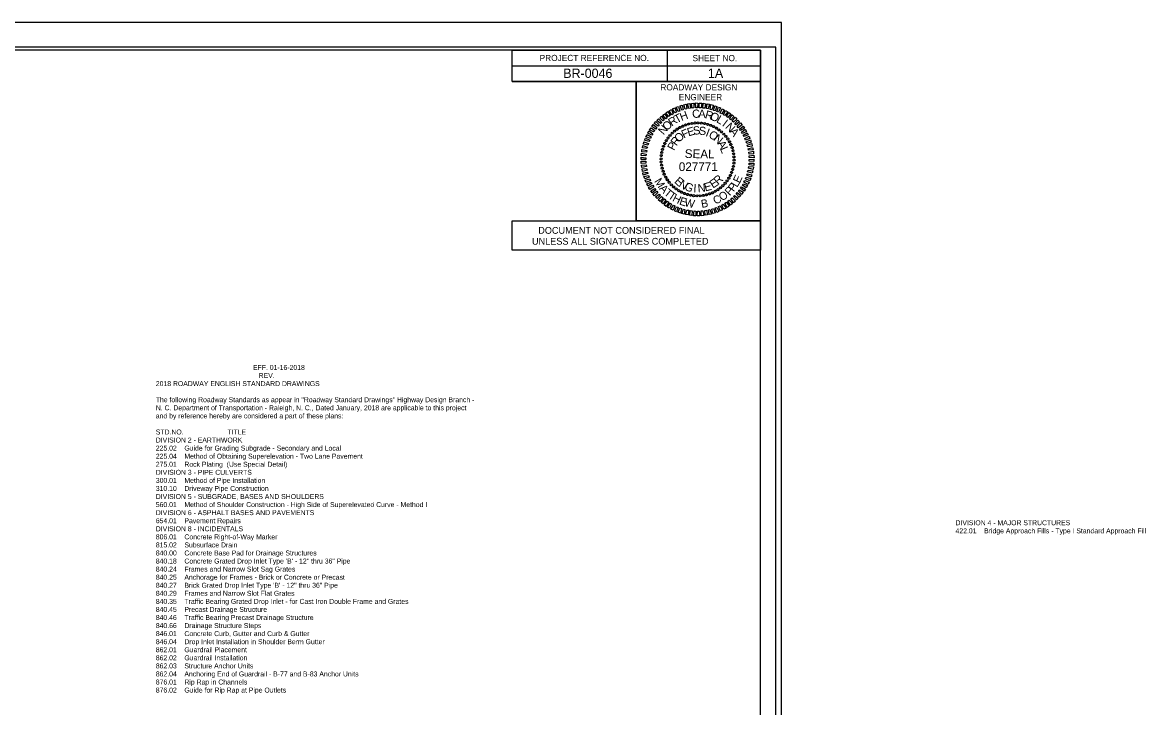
# Model space of a CAD drawing. Extents: x 1983800 to 2121016, y 627229 to 697309.
# Drawn here: x 2052408 to 2110005, y 661964 to 697309 of the extents above; entities that cross this region are included whole.
import ezdxf

# ---------------------------------------------------------------- set-up
doc = ezdxf.new("R2010")
doc.units = 0
for name, color, linetype in [('Sheet Cutting Line CELL', 7, 'Continuous'), ('Sheet Data Field CELL', 7, 'Continuous'), ('Sheet Data Text CELL', 7, 'Continuous'), ('Sheet Plan CELL', 7, 'Continuous'), ('Sheet Plot Border Inside CELL', 7, 'Continuous'), ('Sheet Plot Border Outside CELL', 7, 'Continuous'), ('Sheet Professional Seal CELL', 7, 'Continuous'), ('Sheet Sticker Exception Certification CELL', 7, 'Continuous')]:
    doc.layers.add(name, color=color, linetype=linetype)

msp = doc.modelspace()

# ---------------------------------------------------------------- linework, layer by layer
at = {"layer": 'Sheet Cutting Line CELL'}
msp.add_line((2091544, 697309), (1983800, 697309), dxfattribs=at)
at = {"layer": 'Sheet Plan CELL'}
for p, q in [((2085656, 695866), (2085656, 694266)), ((2077653, 695066), (2090456, 695066)), ((2077653, 694266), (2090456, 694266)), ((2077653, 694266), (2090456, 694266)), ((2084056, 694266), (2084056, 687069))]:
    msp.add_line(p, q, dxfattribs=at)
for points in [[(2090456, 695869), (1994456, 695869), (1994456, 628669), (2090456, 628669)], [(2077653, 695869), (2090456, 695869), (2090456, 694266), (2077653, 694266)], [(2084056, 694266), (2090456, 694266), (2090456, 687066), (2084056, 687066)]]:
    msp.add_lwpolyline(points, close=True, dxfattribs=at)
at = {"layer": 'Sheet Plot Border Inside CELL'}
msp.add_lwpolyline([(1984632, 628509), (2091256, 628509), (2091256, 696029), (1984632, 696029)], close=True, dxfattribs=at)
at = {"layer": 'Sheet Plot Border Outside CELL'}
msp.add_lwpolyline([(1983800, 627229), (2091544, 627229), (2091544, 697309), (1983800, 697309)], close=True, dxfattribs=at)
at = {"layer": 'Sheet Professional Seal CELL'}
for p, q in [((2086162, 691799), (2086162, 691799)), ((2086305, 691885), (2086305, 691885)), ((2086451, 691960), (2086451, 691960)), ((2086601, 692020), (2086601, 692020)), ((2086758, 692065), (2086758, 692065)), ((2086923, 692095), (2086923, 692095)), ((2087085, 692118), (2087085, 692118)), ((2087250, 692121), (2087250, 692121)), ((2087415, 692110), (2087415, 692110)), ((2087576, 692084), (2087576, 692084)), ((2087733, 692050), (2087733, 692050)), ((2087891, 691998), (2087891, 691998)), ((2088041, 691930), (2088041, 691930)), ((2088187, 691855), (2088187, 691855)), ((2088322, 691761), (2088322, 691761)), ((2085600, 691210), (2085600, 691210)), ((2085693, 691345), (2085693, 691345)), ((2085795, 691476), (2085795, 691476)), ((2085907, 691593), (2085907, 691593)), ((2086031, 691705), (2086031, 691705)), ((2088453, 691660), (2088453, 691660)), ((2088570, 691548), (2088570, 691548)), ((2088682, 691424), (2088682, 691424)), ((2088776, 691293), (2088776, 691293)), ((2085371, 690599), (2085371, 690599)), ((2085405, 690756), (2085405, 690756)), ((2085457, 690914), (2085457, 690914)), ((2085525, 691064), (2085525, 691064)), ((2088862, 691150), (2088862, 691150)), ((2088937, 691004), (2088937, 691004)), ((2088997, 690854), (2088997, 690854)), ((2089042, 690696), (2089042, 690696)), ((2085333, 690273), (2085333, 690273)), ((2085337, 690108), (2085337, 690108)), ((2085345, 690438), (2085345, 690438)), ((2087216, 690239), (2087216, 690239)), ((2089072, 690531), (2089072, 690531)), ((2089087, 690040), (2089087, 690040)), ((2089095, 690370), (2089095, 690370)), ((2089098, 690205), (2089098, 690205)), ((2085360, 689946), (2085360, 689946)), ((2085390, 689781), (2085390, 689781)), ((2085435, 689624), (2085435, 689624)), ((2085495, 689474), (2085495, 689474)), ((2088975, 689564), (2088975, 689564)), ((2089027, 689721), (2089027, 689721)), ((2089061, 689879), (2089061, 689879)), ((2085570, 689328), (2085570, 689328)), ((2085656, 689185), (2085656, 689185)), ((2085750, 689054), (2085750, 689054)), ((2085862, 688930), (2085862, 688930)), ((2088525, 688885), (2088525, 688885)), ((2088637, 689001), (2088637, 689001)), ((2088738, 689133), (2088738, 689133)), ((2088832, 689268), (2088832, 689268)), ((2088907, 689414), (2088907, 689414)), ((2085978, 688818), (2085978, 688818)), ((2086110, 688716), (2086110, 688716)), ((2086245, 688623), (2086245, 688623)), ((2086391, 688548), (2086391, 688548)), ((2086541, 688480), (2086541, 688480)), ((2086698, 688428), (2086698, 688428)), ((2086856, 688394), (2086856, 688394)), ((2087017, 688368), (2087017, 688368)), ((2087182, 688356), (2087182, 688356)), ((2087347, 688360), (2087347, 688360)), ((2087508, 688383), (2087508, 688383)), ((2087673, 688413), (2087673, 688413)), ((2087831, 688458), (2087831, 688458)), ((2087981, 688518), (2087981, 688518)), ((2088127, 688593), (2088127, 688593)), ((2088270, 688679), (2088270, 688679)), ((2088401, 688773), (2088401, 688773))]:
    msp.add_line(p, q, dxfattribs=at)
for points in [[(2086050, 692635), (2085930, 692845), (2086046, 692898), (2086132, 692669)], [(2086215, 692714), (2086117, 692931), (2086230, 692976), (2086308, 692736)], [(2086398, 692774), (2086312, 692999), (2086428, 693033), (2086477, 692800)], [(2086578, 692823), (2086500, 693059), (2086627, 693085), (2086657, 692841)], [(2086758, 692864), (2086698, 693104), (2086822, 693115), (2086848, 692875)], [(2086938, 692886), (2086897, 693126), (2087025, 693141), (2087028, 692898)], [(2087126, 692905), (2087107, 693149), (2087231, 693145), (2087216, 692901)], [(2087306, 692901), (2087306, 693145), (2087430, 693141), (2087396, 692898)], [(2087493, 692890), (2087508, 693134), (2087632, 693111), (2087583, 692875)], [(2087673, 692860), (2087707, 693100), (2087831, 693081), (2087763, 692849)], [(2087865, 692819), (2087902, 693063), (2088030, 693033), (2087943, 692800)], [(2088045, 692770), (2088101, 693003), (2088217, 692965), (2088123, 692744)], [(2088213, 692703), (2088300, 692939), (2088405, 692894), (2088300, 692676)], [(2085307, 692091), (2085116, 692245), (2085210, 692331), (2085367, 692151)], [(2085431, 692223), (2085266, 692388), (2085356, 692478), (2085502, 692275)], [(2085581, 692339), (2085420, 692519), (2085521, 692598), (2085652, 692388)], [(2085723, 692451), (2085585, 692643), (2085682, 692714), (2085806, 692496)], [(2085888, 692545), (2085750, 692748), (2085866, 692808), (2085960, 692590)], [(2088382, 692631), (2088476, 692853), (2088592, 692800), (2088465, 692590)], [(2088555, 692545), (2088656, 692759), (2088768, 692695), (2088626, 692500)], [(2088701, 692444), (2088832, 692661), (2088930, 692583), (2088783, 692399)], [(2088855, 692331), (2088993, 692538), (2089091, 692455), (2088926, 692279)], [(2088997, 692215), (2089151, 692410), (2089241, 692320), (2089068, 692159)], [(2084951, 691656), (2084741, 691769), (2084816, 691874), (2085011, 691724)], [(2085063, 691806), (2084861, 691934), (2084932, 692043), (2085112, 691878)], [(2085176, 691949), (2084981, 692095), (2085063, 692193), (2085228, 692016)], [(2089132, 692084), (2089293, 692260), (2089383, 692170), (2089188, 692024)], [(2089263, 691949), (2089436, 692118), (2089515, 692016), (2089316, 691874)], [(2089376, 691803), (2089560, 691960), (2089631, 691851), (2089421, 691731)], [(2089473, 691649), (2089672, 691791), (2089743, 691679), (2089526, 691574)], [(2084711, 691158), (2084478, 691225), (2084527, 691341), (2084752, 691236)], [(2084786, 691323), (2084553, 691409), (2084610, 691525), (2084823, 691405)], [(2084861, 691495), (2084647, 691589), (2084703, 691705), (2084906, 691566)], [(2089571, 691484), (2089781, 691615), (2089830, 691499), (2089616, 691413)], [(2089646, 691323), (2089867, 691435), (2089916, 691315), (2089683, 691240)], [(2089713, 691146), (2089942, 691244), (2089983, 691128), (2089751, 691068)], [(2084576, 690606), (2084336, 690629), (2084351, 690756), (2084595, 690696)], [(2084606, 690798), (2084373, 690828), (2084400, 690955), (2084636, 690876)], [(2084655, 690978), (2084422, 691026), (2084448, 691150), (2084685, 691056)], [(2089773, 690966), (2090013, 691053), (2090036, 690929), (2089800, 690888)], [(2089818, 690786), (2090055, 690858), (2090077, 690730), (2089841, 690708)], [(2089852, 690606), (2090096, 690659), (2090107, 690531), (2089867, 690516)], [(2084557, 690051), (2084313, 690021), (2084306, 690149), (2084550, 690141)], [(2084553, 690239), (2084310, 690228), (2084310, 690355), (2084553, 690329)], [(2084557, 690426), (2084313, 690434), (2084321, 690558), (2084565, 690516)], [(2089875, 690051), (2090118, 690044), (2090111, 689920), (2089867, 689961)], [(2089875, 690426), (2090118, 690456), (2090126, 690329), (2089882, 690336)], [(2089878, 690239), (2090122, 690250), (2090122, 690123), (2089878, 690149)], [(2084580, 689871), (2084336, 689819), (2084325, 689946), (2084565, 689961)], [(2084613, 689691), (2084377, 689620), (2084355, 689748), (2084591, 689770)], [(2084658, 689511), (2084418, 689425), (2084396, 689549), (2084632, 689590)], [(2089777, 689500), (2090010, 689451), (2089983, 689328), (2089747, 689421)], [(2089826, 689680), (2090058, 689650), (2090032, 689523), (2089796, 689601)], [(2089856, 689871), (2090096, 689849), (2090081, 689721), (2089837, 689781)], [(2084718, 689331), (2084490, 689234), (2084448, 689350), (2084681, 689410)], [(2084786, 689155), (2084565, 689043), (2084516, 689163), (2084748, 689238)], [(2084861, 688994), (2084651, 688863), (2084602, 688979), (2084816, 689065)], [(2084958, 688829), (2084760, 688686), (2084688, 688799), (2084906, 688904)], [(2089571, 688983), (2089785, 688889), (2089728, 688773), (2089526, 688911)], [(2089646, 689155), (2089878, 689069), (2089822, 688953), (2089608, 689073)], [(2089721, 689320), (2089953, 689253), (2089905, 689136), (2089680, 689241)], [(2085056, 688675), (2084872, 688518), (2084801, 688626), (2085011, 688746)], [(2085168, 688529), (2084996, 688360), (2084917, 688461), (2085116, 688604)], [(2085300, 688394), (2085138, 688218), (2085048, 688308), (2085243, 688454)], [(2085435, 688263), (2085281, 688068), (2085191, 688158), (2085363, 688319)], [(2089125, 688386), (2089316, 688233), (2089222, 688146), (2089065, 688326)], [(2089256, 688529), (2089451, 688383), (2089368, 688285), (2089203, 688461)], [(2089368, 688671), (2089571, 688544), (2089500, 688435), (2089320, 688600)], [(2089481, 688821), (2089691, 688709), (2089616, 688604), (2089421, 688754)], [(2085577, 688146), (2085438, 687940), (2085341, 688023), (2085506, 688199)], [(2085731, 688034), (2085600, 687816), (2085502, 687895), (2085648, 688079)], [(2085877, 687933), (2085776, 687719), (2085663, 687783), (2085806, 687978)], [(2086050, 687846), (2085956, 687625), (2085840, 687678), (2085967, 687888)], [(2086218, 687775), (2086132, 687539), (2086027, 687584), (2086132, 687801)], [(2086387, 687708), (2086331, 687475), (2086215, 687513), (2086308, 687734)], [(2088217, 687764), (2088315, 687546), (2088202, 687501), (2088123, 687741)], [(2088382, 687843), (2088502, 687633), (2088386, 687580), (2088300, 687809)], [(2088543, 687933), (2088682, 687730), (2088566, 687670), (2088472, 687888)], [(2088708, 688026), (2088847, 687835), (2088750, 687764), (2088626, 687981)], [(2088851, 688139), (2089012, 687959), (2088911, 687880), (2088780, 688090)], [(2089001, 688255), (2089166, 688090), (2089076, 688000), (2088930, 688203)], [(2086567, 687659), (2086530, 687415), (2086402, 687445), (2086488, 687678)], [(2086758, 687618), (2086725, 687378), (2086601, 687396), (2086668, 687629)], [(2086938, 687588), (2086923, 687344), (2086800, 687366), (2086848, 687603)], [(2087126, 687576), (2087126, 687333), (2087002, 687336), (2087036, 687580)], [(2087306, 687573), (2087325, 687329), (2087201, 687333), (2087216, 687576)], [(2087493, 687591), (2087535, 687351), (2087407, 687336), (2087403, 687580)], [(2087673, 687614), (2087733, 687374), (2087610, 687363), (2087583, 687603)], [(2087853, 687655), (2087932, 687419), (2087805, 687393), (2087775, 687636)], [(2088033, 687704), (2088120, 687479), (2088003, 687445), (2087955, 687678)]]:
    msp.add_lwpolyline(points, close=True, dxfattribs=at)
for centre, major_axis in [((2086032, 691701), (-34, 42)), ((2086164, 691798), (-30.2, 44.8)), ((2086304, 691884), (-26.2, 47.2)), ((2086451, 691957), (-22, 49.3)), ((2086604, 692017), (-17.6, 51.1)), ((2086761, 692064), (-13.1, 52.4)), ((2086922, 692097), (-8.4, 53.3)), ((2087085, 692115), (-3.8, 53.9)), ((2087249, 692120), (0.9, 54)), ((2087413, 692110), (5.6, 53.7)), ((2087575, 692085), (10.3, 53)), ((2087734, 692047), (14.9, 51.9)), ((2087890, 691995), (19.4, 50.4)), ((2088041, 691929), (23.7, 48.5)), ((2088185, 691851), (27.8, 46.3)), ((2088322, 691761), (31.7, 43.7)), ((2085604, 691208), (-46.3, 27.8)), ((2085694, 691344), (-43.7, 31.7)), ((2085796, 691473), (-40.8, 35.4)), ((2085909, 691592), (-37.5, 38.8)), ((2088450, 691658), (35.4, 40.8)), ((2088569, 691545), (38.8, 37.5)), ((2088678, 691423), (42, 34)), ((2088775, 691291), (44.8, 30.2)), ((2088861, 691151), (47.2, 26.2)), ((2085370, 690598), (-53, 10.3)), ((2085408, 690757), (-51.9, 14.9)), ((2085460, 690913), (-50.4, 19.4)), ((2085525, 691063), (-48.5, 23.7)), ((2088934, 691004), (49.3, 22)), ((2088994, 690851), (51.1, 17.6)), ((2089041, 690694), (52.4, 13.1)), ((2089074, 690533), (53.3, 8.4)), ((2085335, 690272), (-54, 0.9)), ((2085340, 690108), (-53.9, -3.8)), ((2085345, 690435), (-53.7, 5.6)), ((2089087, 690042), (53.7, -5.6)), ((2089092, 690370), (53.9, 3.8)), ((2089097, 690206), (54, -0.9)), ((2085358, 689945), (-53.3, -8.4)), ((2085391, 689784), (-52.4, -13.1)), ((2085437, 689626), (-51.1, -17.6)), ((2085498, 689474), (-49.3, -22)), ((2088907, 689414), (48.5, -23.7)), ((2088972, 689565), (50.4, -19.4)), ((2089024, 689720), (51.9, -14.9)), ((2089062, 689880), (53, -10.3)), ((2085571, 689327), (-47.2, -26.2)), ((2085657, 689187), (-44.8, -30.2)), ((2085754, 689055), (-42, -34)), ((2085863, 688932), (-38.8, -37.5)), ((2085982, 688819), (-35.4, -40.8)), ((2088523, 688886), (37.5, -38.8)), ((2088636, 689005), (40.8, -35.4)), ((2088738, 689133), (43.7, -31.7)), ((2088828, 689270), (46.3, -27.8)), ((2086110, 688717), (-31.7, -43.7)), ((2086247, 688627), (-27.8, -46.3)), ((2086391, 688548), (-23.7, -48.5)), ((2086542, 688483), (-19.4, -50.4)), ((2086697, 688431), (-14.9, -51.9)), ((2086857, 688392), (-10.3, -53)), ((2087019, 688368), (-5.6, -53.7)), ((2087183, 688358), (-0.9, -54)), ((2087347, 688362), (3.8, -53.9)), ((2087510, 688381), (8.4, -53.3)), ((2087671, 688414), (13.1, -52.4)), ((2087828, 688460), (17.6, -51.1)), ((2087981, 688520), (22, -49.3)), ((2088128, 688594), (26.2, -47.2)), ((2088268, 688679), (30.2, -44.8)), ((2088400, 688777), (34, -42))]:
    msp.add_ellipse(centre, major_axis=major_axis, ratio=0.999708, dxfattribs=at)
at = {"layer": 'Sheet Sticker Exception Certification CELL'}
for p, q in [((2077654, 685562), (2077654, 687066)), ((2077654, 687066), (2090456, 687066)), ((2090456, 687066), (2090456, 685562)), ((2090456, 685562), (2077654, 685562))]:
    msp.add_line(p, q, dxfattribs=at)

# ---------------------------------------------------------------- texts
at = {"layer": 'Sheet Data Field CELL'}
for s, p in [('BR-0046', (2080292, 694442)), ('1A', (2087750, 694445))]:
    msp.add_text(s, height=480, dxfattribs=at).set_placement(p)
at = {"layer": 'Sheet Data Text CELL'}
for s, height, p in [('                                                   EFF. 01-16-2018', 256, (2059288, 679381)), ('                                                      REV. ', 256, (2059288, 678965)), ('2018 ROADWAY ENGLISH STANDARD DRAWINGS', 256, (2059288, 678549)), ('The following Roadway Standards as appear in "Roadway Standard Drawings" Highway Design Branch -', 256, (2059288, 677717)), ('N. C. Department of Transportation - Raleigh, N. C., Dated January, 2018 are applicable to this project', 255.998, (2059288, 677301)), ('and by reference hereby are considered a part of these plans:', 256, (2059288, 676885)), ('STD.NO.                       TITLE', 256, (2059288, 676053)), ('DIVISION 2 - EARTHWORK', 256, (2059288, 675637)), ('225.02    Guide for Grading Subgrade - Secondary and Local', 256, (2059288, 675221)), ('225.04    Method of Obtaining Superelevation - Two Lane Pavement', 256, (2059288, 674805)), ('275.01    Rock Plating  (Use Special Detail)', 256, (2059288, 674389)), ('DIVISION 3 - PIPE CULVERTS', 256, (2059288, 673973)), ('300.01    Method of Pipe Installation ', 256, (2059288, 673557)), ('310.10    Driveway Pipe Construction', 256, (2059288, 673141)), ('DIVISION 5 - SUBGRADE, BASES AND SHOULDERS', 256, (2059288, 672725)), ('560.01    Method of Shoulder Construction - High Side of Superelevated Curve - Method I', 256, (2059288, 672309)), ('654.01    Pavement Repairs', 256, (2059288, 671477)), ('DIVISION 6 - ASPHALT BASES AND PAVEMENTS', 256, (2059288, 671893)), ('DIVISION 4 - MAJOR STRUCTURES', 256, (2100514, 671372)), ('DIVISION 8 - INCIDENTALS', 256, (2059288, 671061)), ('422.01    Bridge Approach Fills - Type I Standard Approach Fill', 256, (2100514, 670956)), ('806.01    Concrete Right-of-Way Marker', 256, (2059288, 670645)), ('815.02    Subsurface Drain', 256, (2059288, 670229)), ('840.00    Concrete Base Pad for Drainage Structures', 256, (2059288, 669813)), ('840.18    Concrete Grated Drop Inlet Type \'B\' - 12" thru 36" Pipe', 256, (2059288, 669397)), ('840.24    Frames and Narrow Slot Sag Grates', 256, (2059288, 668981)), ('840.25    Anchorage for Frames - Brick or Concrete or Precast', 256, (2059288, 668565)), ('840.27    Brick Grated Drop Inlet Type \'B\' - 12" thru 36" Pipe', 256, (2059288, 668149)), ('840.29    Frames and Narrow Slot Flat Grates', 256, (2059288, 667733)), ('840.35    Traffic Bearing Grated Drop Inlet - for Cast Iron Double Frame and Grates', 256, (2059288, 667317)), ('840.45    Precast Drainage Structure', 256, (2059288, 666902)), ('840.46    Traffic Bearing Precast Drainage Structure', 256, (2059288, 666486)), ('840.66    Drainage Structure Steps', 256, (2059288, 666070)), ('846.01    Concrete Curb, Gutter and Curb & Gutter', 256, (2059288, 665654)), ('846.04    Drop Inlet Installation in Shoulder Berm Gutter', 256, (2059288, 665238)), ('862.01    Guardrail Placement', 256, (2059288, 664822)), ('862.02    Guardrail Installation', 256, (2059288, 664406)), ('862.03    Structure Anchor Units', 256, (2059288, 663990)), ('862.04    Anchoring End of Guardrail - B-77 and B-83 Anchor Units', 256, (2059288, 663574)), ('876.01    Rip Rap in Channels', 256, (2059288, 663158)), ('876.02    Guide for Rip Rap at Pipe Outlets', 256, (2059288, 662742))]:
    msp.add_text(s, height=height, dxfattribs=at).set_placement(p)
at = {"layer": 'Sheet Plan CELL'}
for s, height, p in [('PROJECT REFERENCE NO.', 320.01, (2079074, 695312)), ('SHEET NO.', 320, (2086955, 695306)), ('ROADWAY DESIGN', 320.01, (2085298, 693798)), ('ENGINEER', 320, (2086248, 693290))]:
    msp.add_text(s, height=height, dxfattribs=at).set_placement(p)
at = {"layer": 'Sheet Professional Seal CELL'}
for s, height, rotation, p in [('R', 423, 35.02051, (2085888, 691926)), ('T', 423, 27.81977, (2086143, 692091)), ('H', 423, 20.61948, (2086387, 692215)), ('C', 423, 6.21987, (2086957, 692365)), ('A', 423, 359.02032, (2087253, 692388)), ('R', 423, 344.6211, (2087568, 692373)), ('O', 423, 337.42116, (2087820, 692316)), ('L', 423, 330.22088, (2088150, 692178)), ('N', 423, 49.4235, (2085457, 691476)), ('O', 423, 42.22174, (2085630, 691694)), ('F', 423, 25.96703, (2086507, 691311)), ('E', 423, 16.61107, (2086747, 691424)), ('S', 423, 7.25561, (2087006, 691503)), ('S', 423, 357.9004, (2087276, 691506)), ('I', 423, 339.1896, (2087598, 691454)), ('I', 423, 323.02014, (2088453, 691998)), ('N', 423, 315.81891, (2088615, 691881)), ('A', 423, 308.61715, (2088836, 691660)), ('R', 423, 54.03965, (2086128, 690906)), ('O', 423, 44.68124, (2086260, 691090)), ('O', 423, 329.83348, (2087748, 691401)), ('N', 423, 320.47661, (2088000, 691251)), ('P', 423, 63.39889, (2086008, 690666)), ('SEAL', 449.9, 359, (2086552, 690314)), ('A', 423, 301.76027, (2088213, 691056)), ('L', 423, 292.40085, (2088360, 690798)), ('E', 412, 65.34584, (2089393, 688983)), ('M', 412, 301.88628, (2084968, 689115)), ('A', 412, 312.56216, (2085215, 688718)), ('E', 423, 318.27689, (2085986, 689065)), ('N', 423, 327.63396, (2086211, 688863)), ('G', 423, 336.99024, (2086496, 688694)), ('I', 423, 355.7012, (2086987, 688551)), ('N', 423, 5.05639, (2087238, 688540)), ('E', 423, 14.41176, (2087610, 688585)), ('E', 423, 33.12409, (2088007, 688731)), ('R', 423, 42.48141, (2088273, 688908)), ('P', 412, 52.95266, (2089073, 688545)), ('L', 412, 59.53564, (2089255, 688769)), ('T', 412, 320.74796, (2085452, 688449)), ('T', 412, 327.04472, (2085659, 688266)), ('H', 412, 333.34149, (2085885, 688107)), ('E', 412, 342.58629, (2086245, 687921)), ('C', 412, 26.79245, (2088136, 687900)), ('O', 412, 35.66517, (2088485, 688070)), ('P', 412, 46.36967, (2088866, 688344)), ('W', 412, 349.16927, (2086517, 687825)), ('B', 412, 10.22051, (2087431, 687735))]:
    msp.add_text(s, height=height, rotation=rotation, dxfattribs=at).set_placement(p)
msp.add_text('027771', height=449.9, dxfattribs=at).set_placement((2086249, 689638))
at = {"layer": 'Sheet Sticker Exception Certification CELL'}
for s, p in [('DOCUMENT NOT CONSIDERED FINAL', (2079002, 686404)), ('UNLESS ALL SIGNATURES COMPLETED', (2078678, 685841))]:
    msp.add_text(s, height=352, dxfattribs=at).set_placement(p)

doc.saveas('drawing.dxf')
